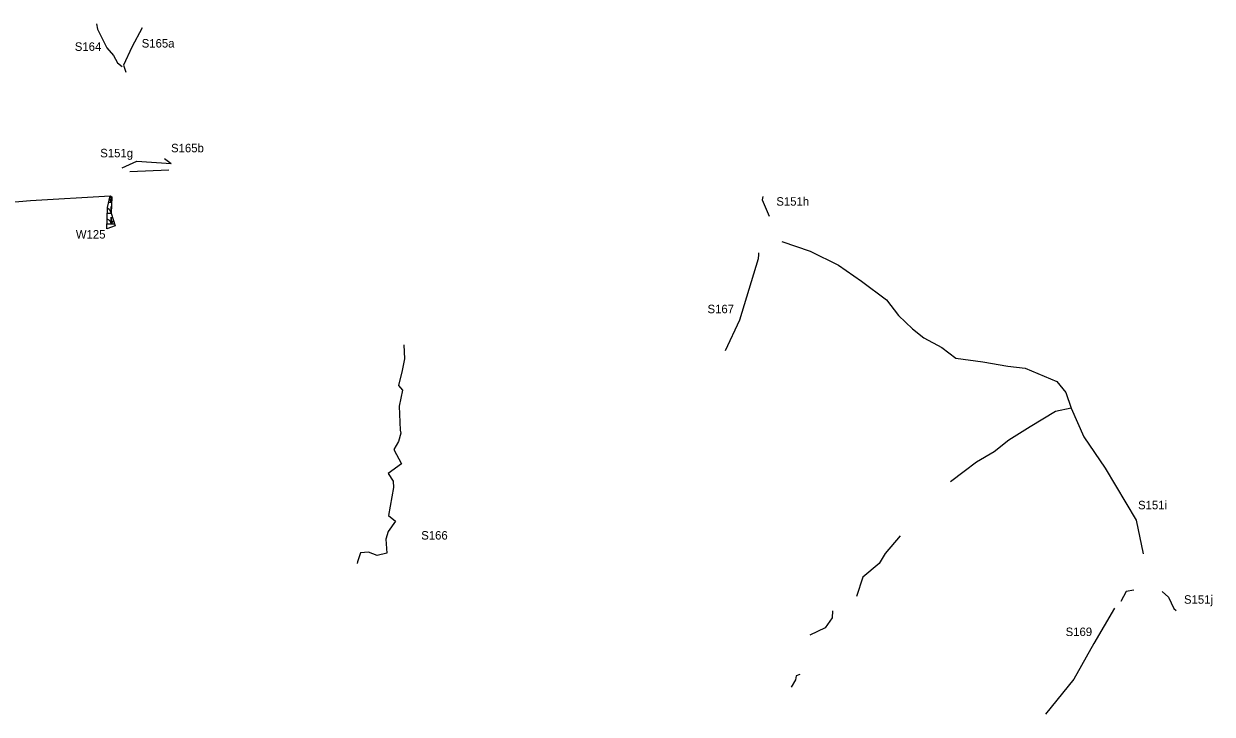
# Model space of a CAD drawing. Extents: x 1253697 to 1278588, y 912189 to 981699.
# Drawn here: x 1275785 to 1278588, y 980071 to 981699 of the extents above; entities that cross this region are included whole.
import ezdxf

# ---------------------------------------------------------------- set-up
doc = ezdxf.new("R2010")
doc.units = 0
doc.layers.add('Exist Environmental Wetland Boundary', color=7, linetype='Continuous')
doc.layers.add('Exist Hydro Jurisdictional Stream or Body of Water Mitigable', color=7, linetype='Continuous')

msp = doc.modelspace()

# ---------------------------------------------------------------- linework, layer by layer
at = {"layer": 'Exist Environmental Wetland Boundary'}
msp.add_lwpolyline([(1275981.7, 981215.5), (1275983.2, 981266.1), (1275988.9, 981293.1), (1275992.8, 981291.4), (1275991.4, 981252.4), (1276001.1, 981223)], close=True, dxfattribs=at)
for points in [[(1275985.8, 981278.6), (1275991.3, 981278.6), (1275991.3, 981292.1)], [(1275991.3, 981292.1), (1275991.3, 981278.6), (1275992.3, 981278.6)], [(1275982.8, 981252.8), (1275991.3, 981252.8), (1275991.3, 981268.6), (1275991.3, 981252.8), (1275991.4, 981252.8)], [(1275982.7, 981227), (1275991.3, 981227), (1275991.3, 981242.8), (1275991.3, 981227), (1275999.8, 981227)]]:
    msp.add_lwpolyline(points, dxfattribs=at)
for centre, radius, start, end in [((1275979.1, 981277.7), 12.3, 4.1403, 46.4347), ((1276009.6, 981272.5), 19.2, 153.1318, 161.6222), ((1275979.1, 981251.9), 12.3, 4.1403, 67.535), ((1276009.6, 981246.7), 19.2, 160.6506, 161.6222), ((1275979.1, 981226.1), 12.3, 4.1403, 67.535), ((1276009.6, 981220.9), 19.2, 130.9006, 161.6222)]:
    msp.add_arc(centre, radius, start, end, dxfattribs=at)
at = {"layer": 'Exist Hydro Jurisdictional Stream or Body of Water Mitigable'}
for p, q in [((1276117.1, 981381.3), (1276132.7, 981369.5)), ((1276035.3, 981350.5), (1276127.5, 981355))]:
    msp.add_line(p, q, dxfattribs=at)
for points in [[(1275956.8, 981699.2), (1275959.6, 981686.3), (1275981.6, 981642.7), (1275997, 981624.7), (1276006.5, 981606.7), (1276017.3, 981598.3)], [(1276064.4, 981689.2), (1276040.5, 981643.8), (1276020.4, 981601.9), (1276026.1, 981585)], [(1276017.5, 981359.3), (1276052.3, 981374.9), (1276132.7, 981369.5)], [(1275002.8, 981074.7), (1275065.7, 981145.8), (1275091.8, 981165.8), (1275226.7, 981225.9), (1275353.1, 981250.2), (1275443.4, 981260.5), (1275584.2, 981268), (1275635.5, 981273.8), (1275746.3, 981278), (1275801, 981282.2), (1275988.9, 981293.1)], [(1277528.2, 981292.1), (1277526.5, 981284), (1277543.5, 981245.7)], [(1277572.9, 981185.5), (1277639.8, 981162.6), (1277707.1, 981130.2), (1277761.1, 981092.1), (1277820, 981047.9), (1277848.3, 981011.6), (1277881.3, 980979.6), (1277908.2, 980958.3), (1277950.5, 980935.7), (1277983.7, 980910.6), (1278047.3, 980901.9), (1278105.9, 980891.6), (1278146.7, 980886.8), (1278221.8, 980855.2), (1278242.6, 980829.4), (1278255.6, 980792.3), (1278285.1, 980725.1), (1278336.1, 980651.1), (1278408.5, 980528.3), (1278425.2, 980449.3)], [(1277518.5, 981158.8), (1277517.9, 981155), (1277517.8, 981144.5), (1277473.5, 981000.5), (1277439.4, 980927.5)], [(1276682, 980942.4), (1276683.7, 980908.7), (1276678.2, 980881.4), (1276669.4, 980846.5), (1276678.4, 980835.1), (1276670.6, 980797.2), (1276672.9, 980740.6), (1276675, 980733.4), (1276669.5, 980713.7), (1276658.5, 980695.6), (1276676, 980661.4), (1276644.6, 980639), (1276656.7, 980620.5), (1276657.3, 980606), (1276645.7, 980539.8), (1276661.8, 980525.9), (1276645.2, 980501.8), (1276639.3, 980483.9), (1276641.5, 980450.6), (1276618.8, 980445), (1276598.8, 980452.8), (1276579.7, 980451.7), (1276572.7, 980430.2), (1276572.1, 980426.2)], [(1278255.6, 980792.3), (1278218.7, 980784.6), (1278159.1, 980748.6), (1278108.3, 980716.9), (1278073.8, 980689.9), (1278032.1, 980665.6), (1278003.1, 980643.4), (1277970.8, 980618.8)], [(1277852.3, 980491.3), (1277816.8, 980449.8), (1277803.1, 980426.6), (1277764.6, 980394.4), (1277749.7, 980348.7)], [(1278403.1, 980363.3), (1278385.1, 980360.3), (1278372.6, 980336.5)], [(1278470.4, 980360.3), (1278484.8, 980347.2), (1278497.5, 980320.3), (1278503.5, 980315.5)], [(1277692.9, 980314.7), (1277691.8, 980298.4), (1277675.6, 980274.5), (1277639, 980257.5)], [(1278357.7, 980321.2), (1278309.2, 980238), (1278261.8, 980153.5), (1278194.8, 980070.9)], [(1277615.3, 980164.9), (1277606.9, 980161.8), (1277605.5, 980152.4), (1277595, 980134.9)]]:
    msp.add_lwpolyline(points, dxfattribs=at)

# ---------------------------------------------------------------- texts
at = {"layer": 'Exist Environmental Wetland Boundary'}
msp.add_text('W125', height=20, dxfattribs=at).set_placement((1275908.3, 981192.7))
at = {"layer": 'Exist Hydro Jurisdictional Stream or Body of Water Mitigable'}
for s, p in [('S164', (1275905.9, 981635.3)), ('S165a', (1276063.6, 981643.1)), ('S151g', (1275965.8, 981384.2)), ('S165b', (1276132.8, 981396.1)), ('S151h', (1277560.2, 981270.2)), ('S167', (1277398, 981016.6)), ('S151i', (1278413.3, 980554.2)), ('S166', (1276722.8, 980482.8)), ('S151j', (1278521.6, 980331.5)), ('S169', (1278242.5, 980255.3))]:
    msp.add_text(s, height=20, dxfattribs=at).set_placement(p)

doc.saveas('drawing.dxf')
